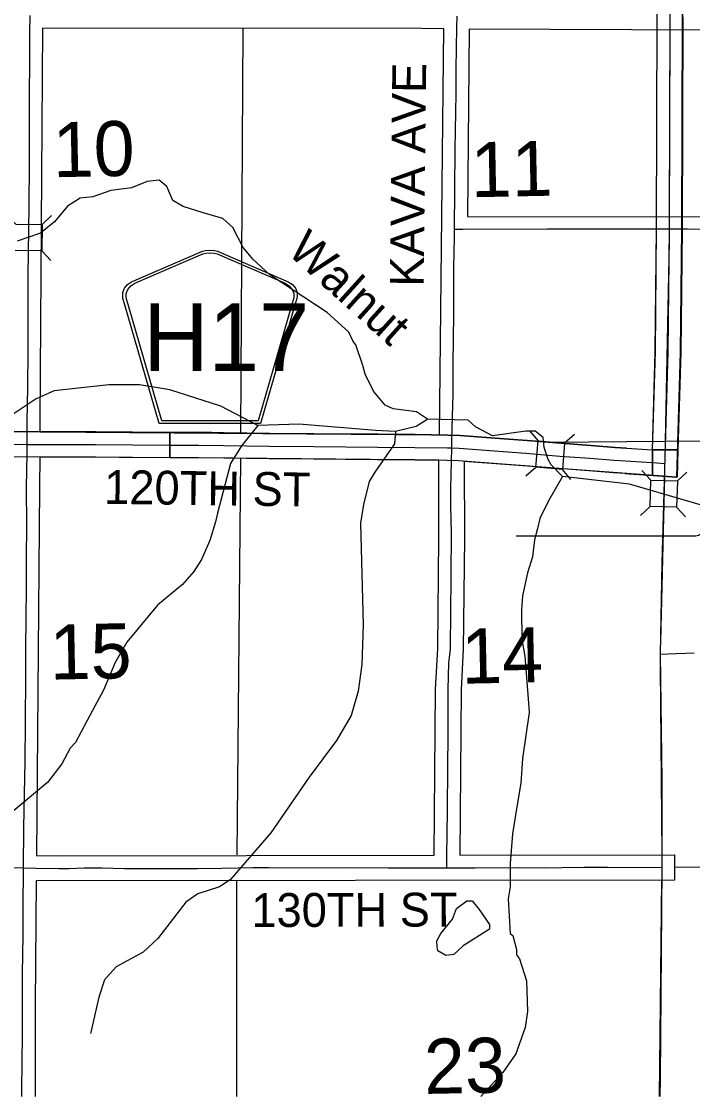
# Model space of a CAD drawing. Extents: x 10133 to 81668, y 7924 to 11018.
# Drawn here: x 11826.5 to 12064.5, y 8510.5 to 8891.7 of the extents above; entities that cross this region are included whole.
import ezdxf

# ---------------------------------------------------------------- set-up
doc = ezdxf.new("R2010")
doc.units = 0
for name, color, linetype in [('tdCoCityStreetMajor', 7, 'Continuous'), ('tdCoCityStreetMinor', 7, 'Continuous'), ('tdCoCorpTxt', 7, 'Continuous'), ('tdCoDirctArrow', 7, 'Continuous'), ('tdCoHydroRiver', 7, 'Continuous'), ('tdCoPriNonDiv', 7, 'Continuous'), ('tdCoRROwnerTxt', 7, 'Continuous'), ('tdCoSecRteBand', 7, 'Continuous'), ('tdCoSectLinePart', 7, 'Continuous'), ('tdCoShieldCoRte', 7, 'Continuous'), ('tdCoShieldStRte', 7, 'Continuous'), ('tdCoStrucNonDivPri', 7, 'Continuous'), ('tdCoStrucSec', 7, 'Continuous'), ('tdCoSurfAsphalt', 7, 'Continuous'), ('tdCoTwpRngTxt', 7, 'Continuous'), ('tdCoUnicrpTwnTxt', 7, 'Continuous')]:
    doc.layers.add(name, color=color, linetype=linetype)

msp = doc.modelspace()

# ---------------------------------------------------------------- linework, layer by layer
at = {"layer": 'tdCoCityStreetMajor'}
for points in [[(11980.11, 8818.02), (11980.38, 8846.28), (11980.64, 8866.11), (11980.71, 8874.88), (11980.86, 8889.49), (11980.98, 8893.53)], [(11979.11, 8740.47), (11979.19, 8743.63), (11979.67, 8759.54), (11979.64, 8770.41), (11979.9, 8787.73), (11979.87, 8793.33)], [(11977.37, 8591.6), (11977.42, 8595.75), (11977.61, 8611.95), (11977.76, 8627.3), (11977.9, 8638.73), (11977.9, 8654.75), (11978.09, 8664.33), (11978.31, 8666.14), (11978.64, 8669.18), (11978.64, 8672.21), (11978.75, 8679.79), (11978.9, 8696.8), (11979.08, 8708.56), (11978.86, 8716.76)]]:
    msp.add_lwpolyline(points, dxfattribs=at)
at = {"layer": 'tdCoCityStreetMinor'}
for points in [[(11827.29, 8591.63), (11827.36, 8605.97), (11827.62, 8617.62), (11827.87, 8629.49), (11827.91, 8642.81), (11828.1, 8659.98), (11828.1, 8670.15), (11828.21, 8679.25), (11828.31, 8691.63), (11828.31, 8701.62), (11828.42, 8712.86), (11828.35, 8726.59), (11828.54, 8738.27), (11828.54, 8741.7), (11828.54, 8749.85), (11828.79, 8762.02), (11828.94, 8775.04), (11828.91, 8794.5), (11828.87, 8801.42), (11829.13, 8817.99), (11829.28, 8826.05), (11829.35, 8841.29), (11829.35, 8849.77), (11829.35, 8867.63), (11829.46, 8875.44), (11829.5, 8887.46), (11829.54, 8893.79)], [(11979.87, 8793.33), (11979.86, 8794.38), (11979.9, 8804.37), (11980.08, 8815.25), (11980.11, 8818.02), (11982.99, 8817.99), (12013.06, 8818.14), (12042.36, 8818.14), (12053.9, 8818.14), (12056.26, 8818.14), (12062.74, 8818.14), (12083.75, 8817.96), (12106.76, 8818.03), (12115.56, 8818.07), (12127.92, 8818.03), (12129.66, 8818.03), (12130.29, 8817.81), (12130.73, 8817.47), (12130.99, 8816.7), (12130.99, 8814.15), (12130.87, 8805.87)], [(11978.86, 8716.76), (11978.82, 8718.26), (11978.82, 8726.36), (11978.97, 8735.6), (11979.11, 8740.47)], [(12053, 8667.35), (12055.69, 8667.51), (12065.05, 8667.85)], [(11751.92, 8591.57), (11754.37, 8591.57), (11762.17, 8591.39), (11770.46, 8591.53), (11780.11, 8591.57), (11788.47, 8591.5), (11797.09, 8591.79), (11803.9, 8591.87), (11817.29, 8591.57), (11823.14, 8591.76), (11827.29, 8591.63)], [(11826.68, 8510.55), (11826.69, 8514.34), (11826.76, 8521.19), (11826.88, 8533.73), (11826.84, 8543.23), (11826.91, 8554.11), (11827.1, 8567.65), (11827.17, 8579.96), (11827.28, 8588.8), (11827.29, 8591.63)], [(11827.29, 8591.63), (11831.57, 8591.51), (11839.74, 8591.32), (11843.3, 8591.39), (11848.73, 8591.65), (11854.98, 8591.62), (11863.01, 8591.39), (11873.41, 8591.39), (11880.73, 8591.43), (11888.91, 8591.43), (11897.56, 8591.51), (11903.41, 8591.65), (11908.58, 8591.76), (11914.21, 8591.76), (11924.49, 8591.58), (11941.54, 8591.69), (11956.6, 8591.62), (11967.4, 8591.62), (11977.37, 8591.6), (11987.45, 8591.58), (12003.12, 8591.72), (12011.9, 8591.62), (12018.12, 8591.77), (12025.96, 8591.82), (12034.34, 8591.82), (12053.62, 8591.78)]]:
    msp.add_lwpolyline(points, dxfattribs=at)
at = {"layer": 'tdCoDirctArrow'}
msp.add_lwpolyline([(12001.95, 8709.33), (12064.86, 8709.26), (12065.4, 8709.29), (12065.73, 8709.34), (12066.15, 8709.44), (12066.57, 8709.58), (12066.97, 8709.75), (12067.36, 8709.96), (12067.73, 8710.2), (12068.07, 8710.47), (12068.39, 8710.77), (12068.68, 8711.1), (12068.94, 8711.45), (12069.17, 8711.82), (12069.36, 8712.22), (12069.52, 8712.62), (12069.64, 8713.04), (12069.73, 8713.47), (12069.77, 8713.91), (12069.78, 8714.35), (12069.93, 8772.22)], dxfattribs=at)
at = {"layer": 'tdCoHydroRiver'}
for points in [[(11970.46, 8750.72), (11966.62, 8753.26), (11958.32, 8754.29), (11955.45, 8755.66), (11951.33, 8760.56), (11948.38, 8766.66), (11947.62, 8769.72), (11945.11, 8777.02), (11944.15, 8778.19), (11942.67, 8781.47), (11934.96, 8788.44), (11914.59, 8801.8), (11908.57, 8807.37), (11905.18, 8811.57), (11901.5, 8818.61), (11897.89, 8821.86), (11890.98, 8823.87), (11883.84, 8826.1), (11880.25, 8828.17), (11878.03, 8833.1), (11875.38, 8835.42), (11871.13, 8834.87), (11865.49, 8832.63), (11858.16, 8831.79), (11851.81, 8829.54), (11847.32, 8828.99), (11842.85, 8826.24), (11838.18, 8820.62), (11833.26, 8816.66), (11824.99, 8813.8)], [(11910.35, 8748.44), (11897.2, 8755.31), (11879.1, 8761.13), (11868.42, 8762.83), (11857.52, 8762.87), (11838.09, 8760.77), (11831.73, 8757.94), (11823.52, 8752.42), (11807.05, 8743.53), (11793.45, 8734.25), (11786.9, 8728.55)], [(11970.46, 8750.72), (11970.22, 8750.48), (11966.48, 8748.05), (11959.17, 8746.25)], [(12018.42, 8730.29), (12014.32, 8734.47), (12013.34, 8736.35), (12011.84, 8740.59), (12011.54, 8744.13), (12008.66, 8746.45), (12005.34, 8746.39), (11993.53, 8744.75), (11987.56, 8747.96), (11984.91, 8750.28), (11970.46, 8750.72)], [(11910.35, 8748.44), (11904.56, 8741.23), (11900.65, 8735), (11896, 8717.4), (11895.35, 8714.31), (11893.34, 8707.64), (11890.38, 8700.95), (11887.62, 8696.64), (11883.67, 8692.04), (11874.78, 8684.72), (11863.86, 8671.64), (11859.71, 8664.42), (11855.61, 8654.59), (11851.7, 8647.37)], [(11959.17, 8746.25), (11952.06, 8746.6), (11925.03, 8748.95), (11910.35, 8748.44)], [(11959.17, 8746.25), (11958.78, 8741.98), (11951.86, 8731.88), (11949.79, 8728.52), (11947.81, 8720.42), (11946.74, 8713.76), (11947.64, 8677.71), (11947.19, 8663.71), (11945.94, 8654.19), (11944.38, 8648.95)], [(12018.42, 8730.29), (12013.37, 8721.67), (12010.41, 8715.46), (12009.52, 8711.89), (12008.41, 8707.85), (12007.81, 8701.91), (12006.01, 8696.16), (12004.25, 8688.03), (12003.85, 8683.02), (12004.02, 8672.54), (12005.07, 8666.61), (12006.28, 8649.96)], [(12227.18, 8670.64), (12226.21, 8671.57), (12211.93, 8675.57), (12203.54, 8681.57), (12199.19, 8686.23), (12196.74, 8690.45), (12196.22, 8693.52), (12194.77, 8694.91), (12188.6, 8695.51), (12182.69, 8695.16), (12180.59, 8693.47), (12178.28, 8690.11), (12176.63, 8689.61), (12173.79, 8689.79), (12169.48, 8692.08), (12165.38, 8696.5), (12157.21, 8702.98), (12149.57, 8706.4), (12139.59, 8708.35), (12097.36, 8712.78), (12073.34, 8718.5), (12042.15, 8727.64), (12018.42, 8730.29)], [(11851.7, 8647.37), (11845.71, 8636.01), (11843.84, 8634.05), (11840.84, 8628.49), (11835.72, 8621.91)], [(11944.38, 8648.95), (11943.49, 8645.61), (11938.21, 8636.72), (11928.51, 8623.72), (11914.9, 8604), (11900.52, 8587.35), (11896.78, 8584.9), (11889.01, 8582.39), (11884.8, 8579.47), (11874.85, 8566.51), (11869.73, 8561.68), (11860.12, 8556.53), (11855.94, 8551.95), (11853.92, 8545.76), (11851.07, 8533.39), (11850.98, 8532.86)], [(12006.28, 8649.96), (12006.58, 8646.63), (12004.23, 8630.4), (12003.67, 8621.58), (12002.15, 8613.22), (12000.64, 8603.66), (11999.87, 8593.17), (11999.78, 8584.88), (11999.15, 8580.61), (11999.85, 8568.31), (12000.81, 8567.62), (12002.08, 8562.67), (12002.12, 8560.77), (12003.09, 8559.37), (12005.6, 8551.6), (12006.03, 8540.72), (12005.19, 8535.02), (12001.81, 8525.72), (11997.19, 8519.01), (11989.48, 8510.55)], [(11835.72, 8621.91), (11820.73, 8609.37), (11810.64, 8601.57), (11805.23, 8598.49), (11789.38, 8594.31)], [(11977.02, 8560.55), (11974.15, 8562.16), (11973.89, 8563.57), (11973.85, 8565.71), (11975.22, 8568.33), (11979.39, 8573.38), (11980.74, 8577.2), (11984.48, 8579.87), (11986.38, 8579.91), (11988.8, 8576.87), (11992.45, 8571.49), (11992.48, 8569.83), (11983.11, 8563.98), (11979.86, 8560.84), (11977.02, 8560.55)]]:
    msp.add_lwpolyline(points, dxfattribs=at)
at = {"layer": 'tdCoPriNonDiv'}
for points in [[(11976.36, 8889.08), (11968.55, 8889.15), (11834.01, 8889.27), (11833.03, 8749.8), (11833.03, 8746.15), (11833.64, 8746.14), (11974.74, 8745.07), (11976.36, 8889.08)], [(12169.68, 8785.4), (12201.63, 8786.13), (12202.63, 8890.2), (12071.72, 8888.56), (11985.35, 8888.99), (11984.65, 8822.5), (12130.42, 8822.46), (12133.73, 8820.83), (12135.26, 8818.12), (12135.37, 8805.71), (12163.5, 8806.21), (12165.69, 8805.84), (12167.73, 8804.63), (12169.29, 8802.39), (12169.88, 8799.76), (12169.68, 8785.4)], [(12059.12, 8734.84), (12058.8, 8730.15), (11983.47, 8735.71), (11983.58, 8708.49), (11983.14, 8669.18), (11982.4, 8654.71), (11981.93, 8596.09), (12058.12, 8596.27), (12058.11, 8587.27), (11831.76, 8587), (11831.34, 8543.22), (11831.32, 8510.55)], [(11839.75, 8595.82), (11972.93, 8596.11), (11973.41, 8654.84), (11974.14, 8669.42), (11974.58, 8708.54), (11974.48, 8736.08), (11889.29, 8737), (11833.02, 8737.15), (11832.85, 8726.56), (11831.81, 8596), (11839.75, 8595.82)]]:
    msp.add_lwpolyline(points, dxfattribs=at)
at = {"layer": 'tdCoSecRteBand'}
msp.add_lwpolyline([(12040.75, 8735.9), (12051.89, 8735.14), (12054.62, 8734.95)], dxfattribs=at)
at = {"layer": 'tdCoSectLinePart'}
msp.add_lwpolyline([(11814.04, 8741.86), (11828.54, 8741.7), (11833.62, 8741.65), (11852.74, 8741.68), (11879.11, 8741.42), (11889.32, 8741.5), (11898.31, 8741.31), (11914.44, 8741.13), (11930.16, 8740.94), (11952.8, 8740.79), (11966.04, 8740.68), (11977.55, 8740.54), (11979.11, 8740.47), (11981.73, 8740.35), (11997.35, 8739.19), (12005.44, 8738.6), (12017.43, 8737.61), (12028.03, 8736.87), (12036.71, 8736.18), (12040.75, 8735.9)], dxfattribs=at)
at = {"layer": 'tdCoShieldCoRte'}
for points in [[(11821.2, 8823.23), (11824.46, 8819.86), (11833.85, 8819.71)], [(11837.14, 8822.91), (11833.85, 8819.71), (11833.7, 8810.33)], [(11836.97, 8806.96), (11833.7, 8810.33), (11824.32, 8810.48)], [(12006.72, 8746.53), (12009.75, 8742.95), (12019.11, 8742.18)], [(12005.4, 8730.57), (12008.98, 8733.6), (12009.75, 8742.95)], [(12022.68, 8745.22), (12019.11, 8742.18), (12018.34, 8732.83)], [(12021.3, 8729.33), (12018.34, 8732.83), (12008.98, 8733.6)], [(12046.56, 8732.52), (12049.77, 8729.1), (12059.15, 8728.8)], [(12062.5, 8731.94), (12059.15, 8728.8), (12058.86, 8719.42)], [(12046.06, 8716.51), (12049.48, 8719.72), (12049.77, 8729.1)], [(12062.07, 8716), (12058.86, 8719.42), (12049.48, 8719.72)]]:
    msp.add_lwpolyline(points, dxfattribs=at)
at = {"layer": 'tdCoStrucNonDivPri'}
for p, q in [((11902.83, 8587.13), (11902.73, 8510.55)), ((12053.56, 8587.28), (12052.62, 8510.55))]:
    msp.add_line(p, q, dxfattribs=at)
for points in [[(11905.04, 8889.07), (11904.23, 8745.83)], [(12056.48, 8888.64), (12056.27, 8822.63)], [(12056.17, 8813.64), (12054.84, 8742.93)], [(12014.04, 8742.48), (12054.84, 8742.93)], [(12054.84, 8742.93), (12054.75, 8739.47)], [(12054.84, 8742.93), (12201.17, 8743.83)], [(11904.16, 8736.84), (11902.88, 8596.17)], [(12054.54, 8730.47), (12053.11, 8671.8)], [(12053.04, 8662.79), (12053.58, 8596.27)], [(12058.12, 8591.84), (12200.31, 8593.72)]]:
    msp.add_lwpolyline(points, dxfattribs=at)
at = {"layer": 'tdCoStrucSec'}
msp.add_lwpolyline([(12057.98, 9067.44), (12058.46, 9043.29), (12056.5, 8893.05), (12056.26, 8818.14), (12055.8, 8774.51), (12053.58, 8699.71), (12053, 8667.35), (12053.63, 8622.55), (12053.62, 8591.78), (12053.06, 8516.92), (12052.96, 8510.55)], dxfattribs=at)
at = {"layer": 'tdCoSurfAsphalt'}
for p, q in [((12041.05, 8740.39), (12050.27, 8739.76)), ((12041.08, 8740.41), (12050.29, 8739.77)), ((12040.46, 8731.43), (12036.4, 8731.71)), ((12040.44, 8731.42), (12058.99, 8730.14))]:
    msp.add_line(p, q, dxfattribs=at)
for points in [[(12050.27, 8739.76), (12051.3, 8774.6), (12051.76, 8818.17), (12052, 8893.09), (12053.96, 9043.28), (12053.48, 9067.35)], [(12050.29, 8739.77), (12051.32, 8774.61), (12051.78, 8818.18), (12052.02, 8893.1), (12053.98, 9043.29), (12053.47, 9069.08)], [(12058.99, 8730.14), (12060.3, 8774.41), (12060.76, 8818.11), (12061, 8893.02), (12062.96, 9043.31), (12062.48, 9067.53)], [(12059.01, 8730.15), (12060.32, 8774.43), (12060.78, 8818.12), (12061.02, 8893.03), (12062.98, 9043.32), (12062.47, 9069.34)], [(12061.02, 8893.03), (12060.78, 8818.12), (12060.32, 8774.43), (12059.29, 8739.77), (12050.29, 8739.77), (12051.32, 8774.61), (12051.78, 8818.18), (12052.02, 8893.1)], [(12041.05, 8740.39), (12037.05, 8740.67), (12028.37, 8741.36), (12017.77, 8742.1), (12005.79, 8743.09), (11997.68, 8743.68), (11981.99, 8744.84), (11977.68, 8745.03), (11966.09, 8745.18), (11952.83, 8745.29), (11930.2, 8745.44), (11914.49, 8745.63), (11898.38, 8745.81), (11889.35, 8746), (11879.12, 8745.92), (11852.76, 8746.18), (11833.64, 8746.15), (11814.06, 8746.36)], [(12041.08, 8740.41), (12037.07, 8740.68), (12028.39, 8741.37), (12017.79, 8742.11), (12005.82, 8743.1), (11997.71, 8743.69), (11982.02, 8744.86), (11977.7, 8745.05), (11966.11, 8745.2), (11952.86, 8745.31), (11930.23, 8745.45), (11914.52, 8745.64), (11898.41, 8745.82), (11889.38, 8746.01), (11879.14, 8745.94), (11852.78, 8746.19), (11833.66, 8746.16), (11814.08, 8746.37)], [(12040.44, 8731.42), (12036.38, 8731.69), (12027.7, 8732.39), (12017.09, 8733.13), (12005.09, 8734.11), (11997.02, 8734.7), (11981.46, 8735.86), (11977.42, 8736.04), (11966, 8736.18), (11952.77, 8736.29), (11930.12, 8736.44), (11914.39, 8736.63), (11898.24, 8736.81), (11889.29, 8737), (11879.11, 8736.92), (11852.72, 8737.18), (11833.59, 8737.15), (11814.02, 8737.36)], [(12036.4, 8731.71), (12027.72, 8732.4), (12017.11, 8733.14), (12005.12, 8734.12), (11997.05, 8734.72), (11981.49, 8735.87), (11977.44, 8736.05), (11966.02, 8736.2), (11952.79, 8736.31), (11930.14, 8736.45), (11914.41, 8736.64), (11898.26, 8736.83), (11889.32, 8737.01), (11879.13, 8736.94), (11852.75, 8737.19), (11833.62, 8737.16), (11814.05, 8737.37)]]:
    msp.add_lwpolyline(points, dxfattribs=at)
for points in [[(11879.13, 8736.94), (11852.75, 8737.19), (11833.62, 8737.16), (11814.05, 8737.37), (11801.61, 8737.34), (11757.84, 8737.23), (11747.77, 8737.26), (11722.6, 8737.23), (11713.8, 8737.17), (11713.8, 8746.17), (11722.57, 8746.23), (11747.78, 8746.26), (11757.84, 8746.23), (11801.59, 8746.34), (11814.08, 8746.37), (11833.66, 8746.16), (11852.78, 8746.19), (11879.14, 8745.94), (11879.14, 8736.94)], [(11879.14, 8745.94), (11889.38, 8746.01), (11898.41, 8745.82), (11914.52, 8745.64), (11930.23, 8745.45), (11952.86, 8745.31), (11966.11, 8745.2), (11977.7, 8745.05), (11982.02, 8744.86), (11997.71, 8743.69), (12005.82, 8743.1), (12017.79, 8742.11), (12028.39, 8741.37), (12037.07, 8740.68), (12041.08, 8740.41), (12050.29, 8739.77), (12050.29, 8730.75), (12036.4, 8731.71), (12027.72, 8732.4), (12017.11, 8733.14), (12005.12, 8734.12), (11997.05, 8734.72), (11981.49, 8735.87), (11977.44, 8736.05), (11966.02, 8736.2), (11952.79, 8736.31), (11930.14, 8736.45), (11914.41, 8736.64), (11898.26, 8736.83), (11889.32, 8737.01), (11879.14, 8736.94)], [(12050.29, 8739.77), (12059.29, 8739.77), (12059.01, 8730.15), (12050.29, 8730.75)]]:
    msp.add_lwpolyline(points, close=True, dxfattribs=at)
at = {"layer": 'tdCoTwpRngTxt'}
for points in [[(12046.56, 8732.52), (12049.77, 8729.1), (12059.15, 8728.8)], [(12062.5, 8731.94), (12059.15, 8728.8), (12058.86, 8719.42)], [(12046.06, 8716.51), (12049.48, 8719.72), (12049.77, 8729.1)], [(12062.07, 8716), (12058.86, 8719.42), (12049.48, 8719.72)]]:
    msp.add_lwpolyline(points, dxfattribs=at)
at = {"layer": 'tdCoUnicrpTwnTxt'}
for points in [[(11875.4, 8749.09), (11863.1, 8791.53), (11862.52, 8793.5), (11862.41, 8794.38), (11862.41, 8795.56), (11863.05, 8797.1), (11864.14, 8798.38), (11865.58, 8799.38), (11890.67, 8810.23), (11891.8, 8810.48), (11893.36, 8810.61), (11894.92, 8810.48), (11896.05, 8810.23), (11921.14, 8799.38), (11922.58, 8798.38), (11923.67, 8797.1), (11924.31, 8795.56), (11924.31, 8794.38), (11924.2, 8793.5), (11923.61, 8791.53), (11911.32, 8749.09)], [(11876.27, 8750.04), (11864.31, 8791.33), (11863.76, 8793.23), (11863.65, 8794.08), (11863.65, 8795.2), (11864.26, 8796.69), (11865.31, 8797.91), (11866.69, 8798.87), (11890.78, 8809.29), (11891.86, 8809.52), (11893.36, 8809.66), (11894.86, 8809.52), (11895.94, 8809.29), (11920.03, 8798.87), (11921.41, 8797.91), (11922.46, 8796.69), (11923.07, 8795.2), (11923.07, 8794.08), (11922.96, 8793.23), (11922.4, 8791.33), (11910.44, 8750.04)]]:
    msp.add_lwpolyline(points, close=True, dxfattribs=at)

# ---------------------------------------------------------------- texts
at = {"layer": 'tdCoCorpTxt'}
msp.add_text('Walnut', height=12, rotation=317.8917, dxfattribs=at).set_placement((11920.33, 8809.69))
at = {"layer": 'tdCoRROwnerTxt'}
for s, rotation, p in [('10', 1.1455, (11837.8, 8836.42)), ('11', 1.1463, (11986.03, 8829.33)), ('15', 1.1456, (11836.72, 8658.32)), ('14', 1.1463, (11982.67, 8656.87)), ('23', 1.1462, (11969.47, 8511.44))]:
    msp.add_text(s, height=19.5, rotation=rotation, dxfattribs=at).set_placement(p)
at = {"layer": 'tdCoShieldStRte'}
for s, rotation, p in [('KAVA AVE', 89.3323, (11969.14, 8797.58)), ('120TH ST', 359.243, (11855.78, 8720.67)), ('130TH ST', 0.1564, (11908.06, 8570.62))]:
    msp.add_text(s, height=12, rotation=rotation, dxfattribs=at).set_placement(p)
at = {"layer": 'tdCoUnicrpTwnTxt'}
msp.add_text('H17', height=24, dxfattribs=at).set_placement((11869.7, 8767.73))

doc.saveas('drawing.dxf')
